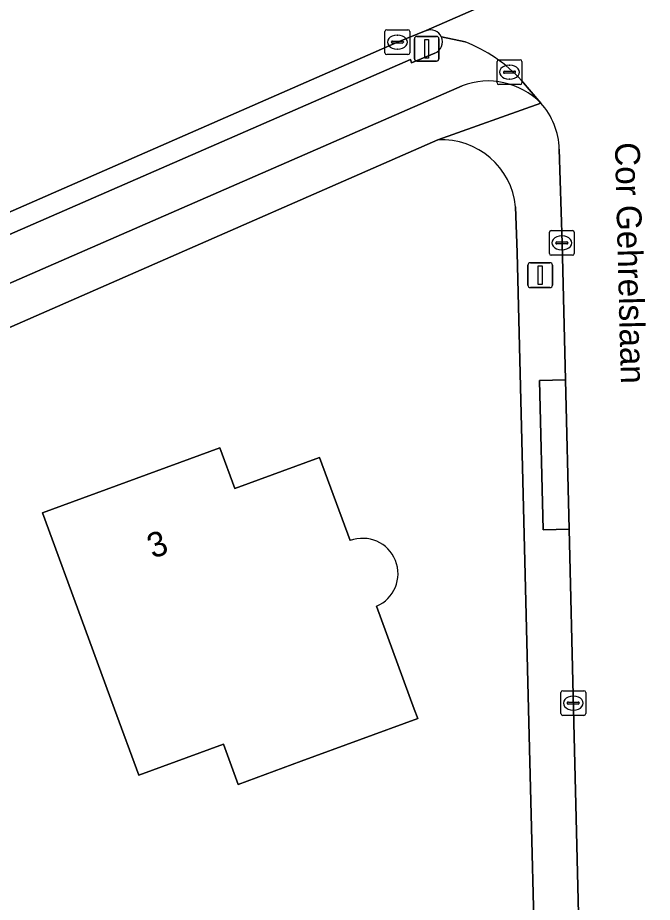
# Model space of a CAD drawing. Extents: x 157320 to 158835, y 386650 to 388491.
# Drawn here: x 157847.2 to 157872.77, y 387742.21 to 387777.87 of the extents above; entities that cross this region are included whole.
import ezdxf

# ---------------------------------------------------------------- set-up
doc = ezdxf.new("R2010")
doc.units = 0
for name, color, linetype in [('IMGEO_Berm_open', 7, 'Continuous'), ('IMGEO_Erf', 7, 'Continuous'), ('IMGEO_Fietspad_open', 7, 'Continuous'), ('IMGEO_Kolk', 7, 'Continuous'), ('IMGEO_Lichtmast', 7, 'Continuous'), ('IMGEO_Openbare_ruimte_label', 7, 'Continuous'), ('IMGEO_Pand', 7, 'Continuous'), ('IMGEO_Pand_nummerreeks', 7, 'Continuous'), ('IMGEO_Rijbaan_lokaal_gesloten', 7, 'Continuous'), ('IMGEO_Rijbaan_lokaal_open', 7, 'Continuous'), ('IMGEO_Voetpad_open', 7, 'Continuous')]:
    doc.layers.add(name, color=color, linetype=linetype)

msp = doc.modelspace()

# ---------------------------------------------------------------- linework, layer by layer
at = {"layer": 'IMGEO_Berm_open'}
for points in [[(157863.66, 387777.349), (157862.5, 387776.887), (157846.023, 387769.675), (157845.904, 387769.619), (157846.099, 387769.175), (157841.159, 387766.996), (157840.962, 387767.442), (157840.947, 387767.435), (157834.528, 387764.625), (157834.309, 387764.533), (157834.534, 387764.055), (157831.038, 387762.539), (157830.821, 387762.995), (157826.947, 387761.265), (157827.147, 387760.797), (157823.696, 387759.296), (157823.485, 387759.737), (157822.606, 387759.344)], [(157823.216, 387758.725), (157835.06, 387763.984), (157843.156, 387767.523), (157863.031, 387776.185), (157863.068, 387776.049), (157864.008, 387776.443)]]:
    msp.add_lwpolyline(points, dxfattribs=at)
for centre, radius, start, end in [((157863.833, 387776.896), 0.484, 24.0706, 110.8883), ((157863.825, 387776.898), 0.491, 291.8875, 23.5117)]:
    msp.add_arc(centre, radius, start, end, dxfattribs=at)
at = {"layer": 'IMGEO_Erf'}
for points in [[(157864.126, 387772.947), (157837.386, 387761.239), (157831.138, 387758.491), (157825.817, 387756.137), (157813.3, 387750.568), (157812.042, 387750), (157807.394, 387747.901), (157801.377, 387745.165), (157794.254, 387741.847)], [(157852.9, 387723.635), (157857.786, 387724.692), (157858.657, 387720.664), (157862.101, 387721.409), (157862.637, 387718.929), (157861.733, 387718.733), (157862.585, 387714.794), (157863.417, 387710.943), (157864.426, 387711.161), (157864.945, 387708.76), (157861.57, 387708.03), (157862.376, 387704.301), (157868.74, 387705.795), (157867.986, 387736.725), (157868.115, 387736.72), (157867.782, 387750), (157867.321, 387768.404), (157867.264, 387770.244)], [(157848.197, 387757.918), (157855.344, 387760.539), (157855.947, 387758.895), (157859.365, 387760.148), (157860.595, 387756.793)], [(157861.66, 387754.15), (157863.181, 387750), (157863.321, 387749.619), (157858.627, 387747.898), (157856.087, 387746.966), (157855.49, 387748.592), (157852.079, 387747.34), (157851.102, 387750), (157849.905, 387753.262), (157848.197, 387757.918)]]:
    msp.add_lwpolyline(points, dxfattribs=at)
for centre, radius, start, end in [((157864.285, 387769.958), 2.993, 5.4769, 93.0414), ((157861.101, 387755.461), 1.425, 293.0782, 110.8159)]:
    msp.add_arc(centre, radius, start, end, dxfattribs=at)
at = {"layer": 'IMGEO_Fietspad_open'}
for points in [[(157865.226, 387776.895), (157864.275, 387777.094)], [(157864.008, 387776.443), (157863.068, 387776.049), (157863.031, 387776.185), (157843.156, 387767.523), (157835.06, 387763.984), (157823.216, 387758.725), (157815.175, 387755.151), (157810.091, 387752.884), (157804.677, 387750.444), (157803.739, 387750), (157797.893, 387747.327), (157788.445, 387742.834), (157770.171, 387734.176), (157769.959, 387734.638)], [(157767.728, 387731.043), (157779.548, 387736.625), (157789.197, 387741.196), (157793.841, 387743.435), (157800.368, 387746.45), (157806.723, 387749.381), (157808.098, 387750), (157812.222, 387751.857), (157817.687, 387754.31), (157825.13, 387757.594), (157830.503, 387759.975), (157836.688, 387762.719), (157865.106, 387775.129)], [(157868.277, 387774.43), (157867.498, 387775.342)]]:
    msp.add_lwpolyline(points, dxfattribs=at)
for centre, radius, start, end in [((157863.825, 387776.898), 0.491, 291.8875, 23.5117), ((157863.101, 387771.348), 5.94, 42.2525, 69.0392), ((157866.154, 387772.343), 2.977, 44.5151, 110.6225)]:
    msp.add_arc(centre, radius, start, end, dxfattribs=at)
at = {"layer": 'IMGEO_Kolk'}
for p, q in [((157861.999, 387776.46), (157861.999, 387777.312)), ((157862.074, 387777.386), (157862.926, 387777.386)), ((157863, 387777.312), (157863, 387776.46)), ((157862.258, 387776.88), (157862.258, 387776.892)), ((157862.301, 387776.929), (157862.699, 387776.929)), ((157862.487, 387777.166), (157862.512, 387777.166)), ((157862.742, 387776.892), (157862.742, 387776.88)), ((157862.696, 387776.843), (157862.298, 387776.843)), ((157862.51, 387776.606), (157862.485, 387776.606)), ((157862.926, 387776.386), (157862.074, 387776.386)), ((157866.593, 387776.176), (157867.445, 387776.176)), ((157866.518, 387775.25), (157866.518, 387776.102)), ((157867.006, 387775.956), (157867.031, 387775.956)), ((157867.519, 387776.102), (157867.519, 387775.25)), ((157866.777, 387775.67), (157866.777, 387775.682)), ((157867.215, 387775.633), (157866.817, 387775.633)), ((157866.82, 387775.719), (157867.218, 387775.719)), ((157867.261, 387775.682), (157867.261, 387775.67)), ((157867.445, 387775.176), (157866.593, 387775.176)), ((157867.029, 387775.396), (157867.004, 387775.396)), ((157868.627, 387768.369), (157868.627, 387769.221)), ((157868.702, 387769.295), (157869.554, 387769.295)), ((157869.115, 387769.075), (157869.14, 387769.075)), ((157869.628, 387769.221), (157869.628, 387768.369)), ((157868.886, 387768.789), (157868.886, 387768.801)), ((157869.324, 387768.752), (157868.926, 387768.752)), ((157868.929, 387768.838), (157869.327, 387768.838)), ((157869.37, 387768.801), (157869.37, 387768.789)), ((157869.138, 387768.515), (157869.113, 387768.515)), ((157869.554, 387768.295), (157868.702, 387768.295)), ((157869.09, 387749.819), (157869.09, 387750.671)), ((157869.165, 387750.745), (157870.017, 387750.745)), ((157869.578, 387750.525), (157869.603, 387750.525)), ((157870.091, 387750.671), (157870.091, 387749.819)), ((157869.349, 387750.239), (157869.349, 387750.251)), ((157869.787, 387750.202), (157869.389, 387750.202)), ((157869.392, 387750.288), (157869.79, 387750.288)), ((157869.833, 387750.251), (157869.833, 387750.239)), ((157869.601, 387749.965), (157869.576, 387749.965)), ((157870.017, 387749.745), (157869.165, 387749.745))]:
    msp.add_line(p, q, dxfattribs=at)
for points in [[(157861.999, 387776.46), (157861.999, 387777.312)], [(157862.074, 387777.386), (157862.926, 387777.386)], [(157863, 387777.312), (157863, 387776.46)], [(157862.926, 387776.386), (157862.074, 387776.386)], [(157866.593, 387776.176), (157867.445, 387776.176)], [(157866.518, 387775.25), (157866.518, 387776.102)], [(157867.519, 387776.102), (157867.519, 387775.25)], [(157867.445, 387775.176), (157866.593, 387775.176)], [(157868.627, 387768.369), (157868.627, 387769.221)], [(157868.702, 387769.295), (157869.554, 387769.295)], [(157869.628, 387769.221), (157869.628, 387768.369)], [(157869.554, 387768.295), (157868.702, 387768.295)], [(157869.09, 387749.819), (157869.09, 387750.671)], [(157869.165, 387750.745), (157870.017, 387750.745)], [(157870.091, 387750.671), (157870.091, 387749.819)], [(157870.017, 387749.745), (157869.165, 387749.745)]]:
    msp.add_lwpolyline(points, dxfattribs=at)
for centre, radius, start, end in [((157862.076, 387777.31), 0.0765, 91.552, 178.448), ((157862.076, 387777.31), 0.0765, 91.552, 178.448), ((157862.924, 387777.31), 0.0765, 1.552, 88.448), ((157862.924, 387777.31), 0.0765, 1.552, 88.448), ((157862.298, 387776.889), 0.0403, 85.8775, 175.7526), ((157862.295, 387776.879), 0.0366, 178.938, 274.7102), ((157862.699, 387776.886), 0.043, 264.8664, 352.4533), ((157862.703, 387776.891), 0.0386, 1.7309, 96.639), ((157862.076, 387776.462), 0.0765, 181.552, 268.448), ((157862.076, 387776.462), 0.0765, 181.552, 268.448), ((157862.924, 387776.462), 0.0765, 271.552, 358.448), ((157862.924, 387776.462), 0.0765, 271.552, 358.448), ((157866.595, 387776.1), 0.0765, 91.552, 178.448), ((157866.595, 387776.1), 0.0765, 91.552, 178.448), ((157867.443, 387776.1), 0.0765, 1.552, 88.448), ((157867.443, 387776.1), 0.0765, 1.552, 88.448), ((157866.817, 387775.679), 0.0403, 85.8775, 175.7526), ((157866.814, 387775.669), 0.0366, 178.938, 274.7102), ((157867.218, 387775.676), 0.043, 264.8664, 352.4533), ((157867.222, 387775.681), 0.0386, 1.7309, 96.639), ((157866.595, 387775.252), 0.0765, 181.552, 268.448), ((157866.595, 387775.252), 0.0765, 181.552, 268.448), ((157867.443, 387775.252), 0.0765, 271.552, 358.448), ((157867.443, 387775.252), 0.0765, 271.552, 358.448), ((157868.704, 387769.219), 0.0765, 91.552, 178.448), ((157868.704, 387769.219), 0.0765, 91.552, 178.448), ((157869.552, 387769.219), 0.0765, 1.552, 88.448), ((157869.552, 387769.219), 0.0765, 1.552, 88.448), ((157868.926, 387768.798), 0.0403, 85.8775, 175.7526), ((157868.923, 387768.788), 0.0366, 178.938, 274.7102), ((157869.327, 387768.795), 0.043, 264.8664, 352.4533), ((157869.331, 387768.8), 0.0386, 1.7309, 96.639), ((157868.704, 387768.371), 0.0765, 181.552, 268.448), ((157868.704, 387768.371), 0.0765, 181.552, 268.448), ((157869.552, 387768.371), 0.0765, 271.552, 358.448), ((157869.552, 387768.371), 0.0765, 271.552, 358.448), ((157869.167, 387750.669), 0.0765, 91.552, 178.448), ((157869.167, 387750.669), 0.0765, 91.552, 178.448), ((157870.015, 387750.669), 0.0765, 1.552, 88.448), ((157870.015, 387750.669), 0.0765, 1.552, 88.448), ((157869.389, 387750.248), 0.0403, 85.8775, 175.7526), ((157869.386, 387750.238), 0.0366, 178.938, 274.7102), ((157869.79, 387750.245), 0.043, 264.8664, 352.4533), ((157869.794, 387750.25), 0.0386, 1.7309, 96.639), ((157869.167, 387749.821), 0.0765, 181.552, 268.448), ((157869.167, 387749.821), 0.0765, 181.552, 268.448), ((157870.015, 387749.821), 0.0765, 271.552, 358.448), ((157870.015, 387749.821), 0.0765, 271.552, 358.448)]:
    msp.add_arc(centre, radius, start, end, dxfattribs=at)
for centre, major_axis, ratio, start_param, end_param in [((157862.486, 387776.886), (-0.387, 0.002), 0.722429, 4.712389, 7.853982), ((157862.511, 387776.886), (-0.39, 0.002), 0.717154, 1.570796, 4.712389), ((157867.005, 387775.676), (-0.387, 0.002), 0.722429, 4.712389, 7.853982), ((157867.03, 387775.676), (-0.39, 0.002), 0.717154, 1.570796, 4.712389), ((157869.114, 387768.795), (-0.387, 0.002), 0.722429, 4.712389, 7.853982), ((157869.139, 387768.795), (-0.39, 0.002), 0.717154, 1.570796, 4.712389), ((157869.577, 387750.245), (-0.387, 0.002), 0.722429, 4.712389, 7.853982), ((157869.602, 387750.245), (-0.39, 0.002), 0.717154, 1.570796, 4.712389)]:
    msp.add_ellipse(centre, major_axis=major_axis, ratio=ratio, start_param=start_param, end_param=end_param, dxfattribs=at)
at = {"layer": 'IMGEO_Lichtmast'}
for p, q in [((157863.186, 387776.219), (157863.186, 387777.019)), ((157863.186, 387777.019), (157863.186, 387776.219)), ((157863.286, 387777.119), (157864.076, 387777.119)), ((157864.076, 387777.119), (157863.286, 387777.119)), ((157864.176, 387777.019), (157864.176, 387776.219)), ((157864.176, 387776.219), (157864.176, 387777.019)), ((157864.076, 387776.119), (157863.286, 387776.119)), ((157863.286, 387776.119), (157864.076, 387776.119)), ((157867.86, 387767.994), (157868.65, 387767.994)), ((157868.65, 387767.994), (157867.86, 387767.994)), ((157867.76, 387767.094), (157867.76, 387767.894)), ((157867.76, 387767.894), (157867.76, 387767.094)), ((157868.75, 387767.894), (157868.75, 387767.094)), ((157868.75, 387767.094), (157868.75, 387767.894)), ((157868.65, 387766.994), (157867.86, 387766.994)), ((157867.86, 387766.994), (157868.65, 387766.994))]:
    msp.add_line(p, q, dxfattribs=at)
for points in [[(157863.606, 387776.994), (157863.756, 387776.994), (157863.756, 387776.244), (157863.606, 387776.244), (157863.606, 387776.994)], [(157868.18, 387767.869), (157868.33, 387767.869), (157868.33, 387767.119), (157868.18, 387767.119), (157868.18, 387767.869)]]:
    msp.add_lwpolyline(points, dxfattribs=at)
for centre, start, end in [((157863.286, 387777.019), 90, 180), ((157863.286, 387777.019), 90, 180), ((157864.076, 387777.019), 0, 90), ((157864.076, 387777.019), 360, 90), ((157863.286, 387776.219), 180, 270), ((157863.286, 387776.219), 180, 270), ((157864.076, 387776.219), 270, 0), ((157864.076, 387776.219), 270, 0), ((157867.86, 387767.894), 90, 180), ((157867.86, 387767.894), 90, 180), ((157868.65, 387767.894), 0, 90), ((157868.65, 387767.894), 360, 90), ((157867.86, 387767.094), 180, 270), ((157867.86, 387767.094), 180, 270), ((157868.65, 387767.094), 270, 0), ((157868.65, 387767.094), 270, 0)]:
    msp.add_arc(centre, 0.1, start, end, dxfattribs=at)
at = {"layer": 'IMGEO_Pand'}
msp.add_lwpolyline([(157860.595, 387756.793), (157859.365, 387760.148), (157855.947, 387758.895), (157855.344, 387760.539), (157848.197, 387757.918), (157849.905, 387753.262), (157851.102, 387750), (157852.079, 387747.34), (157855.49, 387748.592), (157856.087, 387746.966), (157858.627, 387747.898), (157863.321, 387749.619), (157863.181, 387750), (157861.66, 387754.15)], dxfattribs=at)
msp.add_arc((157861.101, 387755.461), 1.425, 293.0782, 110.8159, dxfattribs=at)
at = {"layer": 'IMGEO_Rijbaan_lokaal_gesloten'}
for points in [[(157876.924, 387782.666), (157877.943, 387783.277), (157877.821, 387783.552), (157863.66, 387777.349)], [(157864.275, 387777.094), (157865.226, 387776.895)], [(157867.498, 387775.342), (157868.277, 387774.43)], [(157869.024, 387772.572), (157869.136, 387768.786), (157869.272, 387763.276), (157869.42, 387757.257), (157869.598, 387750), (157869.912, 387737.356), (157870.077, 387730.715), (157870.174, 387726.805), (157870.264, 387723.208), (157870.587, 387710.204), (157870.702, 387705.562), (157872.239, 387642.425)]]:
    msp.add_lwpolyline(points, dxfattribs=at)
for centre, radius, start, end in [((157863.833, 387776.896), 0.484, 24.0706, 110.8883), ((157863.101, 387771.348), 5.94, 42.2525, 69.0392), ((157866.189, 387772.511), 2.836, 1.2282, 42.5765)]:
    msp.add_arc(centre, radius, start, end, dxfattribs=at)
at = {"layer": 'IMGEO_Rijbaan_lokaal_open'}
msp.add_lwpolyline([(157822.606, 387759.344), (157823.485, 387759.737), (157826.947, 387761.265), (157830.821, 387762.995), (157834.309, 387764.533), (157834.528, 387764.625), (157840.947, 387767.435), (157840.962, 387767.442), (157845.799, 387769.569), (157845.904, 387769.619), (157846.023, 387769.675), (157862.5, 387776.887), (157863.66, 387777.349), (157877.821, 387783.552), (157898.534, 387792.559), (157928.836, 387805.602)], dxfattribs=at)
at = {"layer": 'IMGEO_Voetpad_open'}
for points in [[(157865.106, 387775.129), (157836.688, 387762.719), (157830.503, 387759.975), (157825.13, 387757.594), (157817.687, 387754.31), (157812.222, 387751.857), (157808.098, 387750), (157806.723, 387749.381), (157800.368, 387746.45), (157793.841, 387743.435), (157789.197, 387741.196), (157779.548, 387736.625), (157767.728, 387731.043)], [(157868.277, 387774.43), (157864.126, 387772.947)], [(157864.126, 387772.947), (157868.277, 387774.43)], [(157767.54, 387729.135), (157770.315, 387730.462), (157772.157, 387731.342), (157780.283, 387735.18), (157790.1, 387739.844), (157794.254, 387741.847), (157801.377, 387745.165), (157807.394, 387747.901), (157812.042, 387750), (157813.3, 387750.568), (157825.817, 387756.137), (157831.138, 387758.491), (157837.386, 387761.239), (157864.126, 387772.947)], [(157870.077, 387730.715), (157869.037, 387730.689), (157868.872, 387737.33), (157869.912, 387737.356), (157869.598, 387750), (157869.42, 387757.257), (157868.38, 387757.232), (157868.232, 387763.25), (157869.272, 387763.276), (157869.136, 387768.786), (157869.024, 387772.572)], [(157867.264, 387770.244), (157867.321, 387768.404), (157867.782, 387750), (157868.115, 387736.72), (157867.986, 387736.725), (157868.74, 387705.795), (157868.769, 387704.615), (157868.835, 387701.791), (157868.868, 387700.377), (157869.389, 387677.978), (157869.46, 387676.101), (157870.322, 387641.515)]]:
    msp.add_lwpolyline(points, dxfattribs=at)
msp.add_lwpolyline([(157869.42, 387757.257), (157869.272, 387763.276), (157868.232, 387763.25), (157868.38, 387757.232)], close=True, dxfattribs=at)
for centre, radius, start, end in [((157866.154, 387772.343), 2.977, 44.5151, 110.6225), ((157866.189, 387772.511), 2.836, 1.2282, 42.5765), ((157864.285, 387769.958), 2.993, 5.4769, 93.0414)]:
    msp.add_arc(centre, radius, start, end, dxfattribs=at)

# ---------------------------------------------------------------- texts
at = {"layer": 'IMGEO_Openbare_ruimte_label'}
msp.add_text('Cor Gehrelslaan', height=1, rotation=271.4321, dxfattribs=at).set_placement((157871.267, 387772.839))
at = {"layer": 'IMGEO_Pand_nummerreeks'}
msp.add_text('3', height=1, rotation=20.1394, dxfattribs=at).set_placement((157852.641, 387756.055))

doc.saveas('drawing.dxf')
